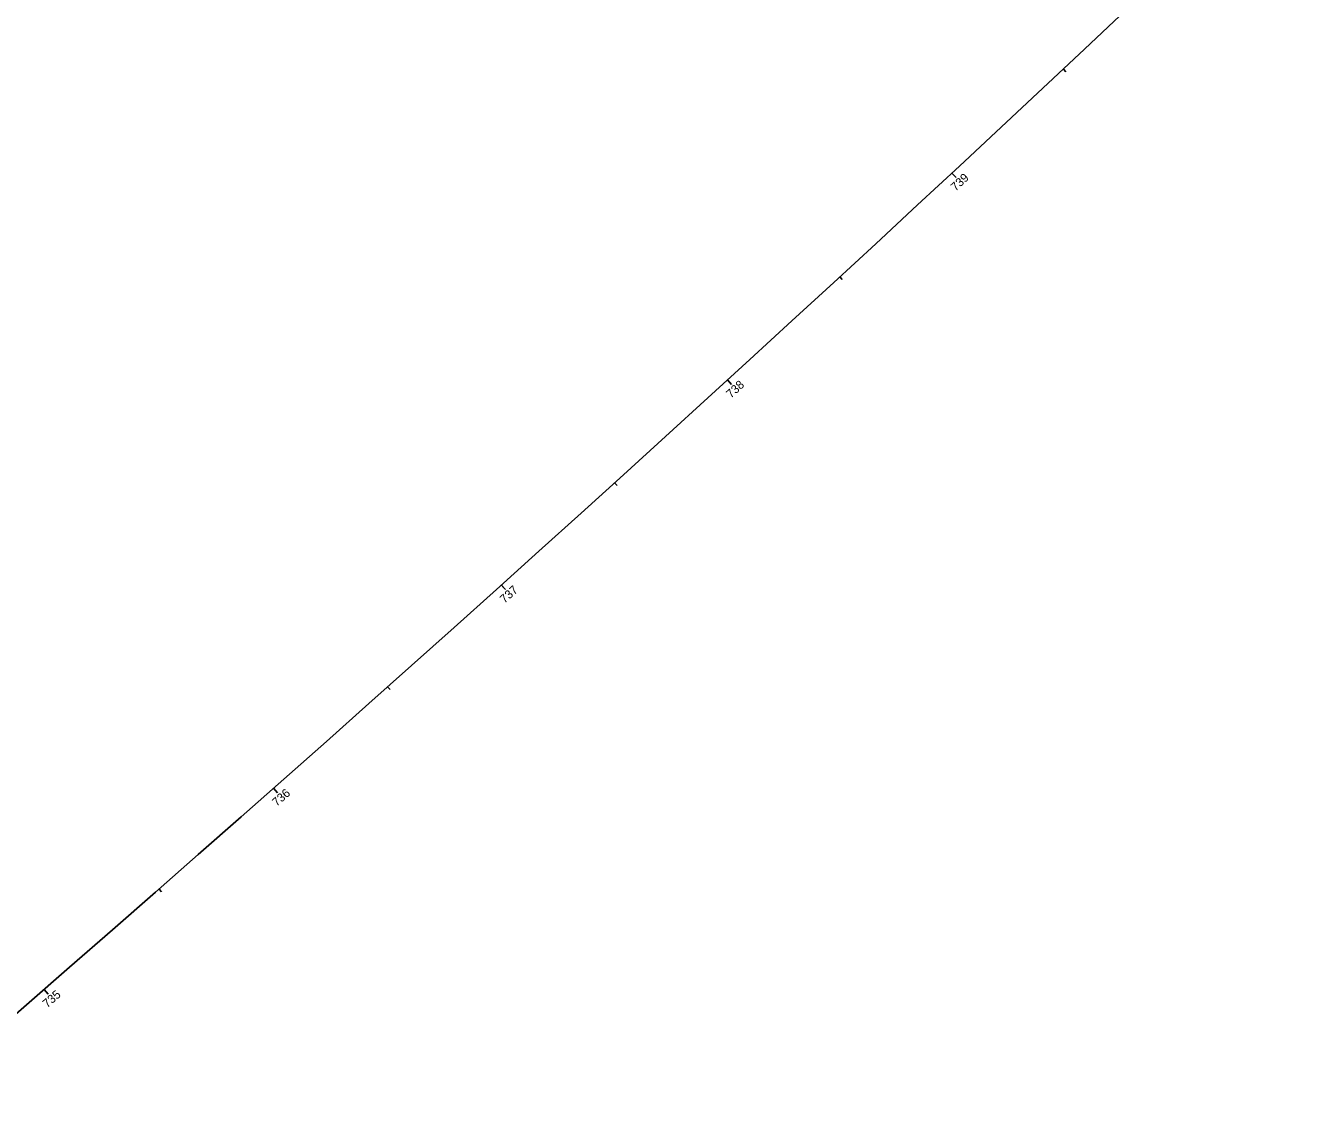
# Model space of a CAD drawing. Extents: x 1492452 to 1496782, y 514026 to 517659.
# Drawn here: x 1494477.9 to 1494892.9, y 515479.1 to 515833 of the extents above; entities that cross this region are included whole.
import ezdxf

# ---------------------------------------------------------------- set-up
doc = ezdxf.new("R2010")
doc.units = 0
for name, color, linetype in [('Default', 7, 'Continuous'), ('DT_X_TIN_Hull', 7, 'Continuous'), ('GE_X_Cells', 7, 'Continuous'), ('UT_X_Water_Cells', 7, 'Continuous'), ('VG_X_Cells', 7, 'Continuous')]:
    doc.layers.add(name, color=color, linetype=linetype)

msp = doc.modelspace()

# ---------------------------------------------------------------- linework, layer by layer
at = {"layer": 'Default'}
msp.add_arc((1486425.91, 524780.42), 12277.67, 302.444021, 313.600151, dxfattribs=at)
at = {"layer": 'DT_X_TIN_Hull'}
for p, q in [((1494818.06, 515818.67), (1494818.88, 515817.79)), ((1494781.5, 515784.57), (1494782.86, 515783.1)), ((1494744.79, 515750.61), (1494745.6, 515749.73)), ((1494707.95, 515716.81), (1494709.3, 515715.34)), ((1494670.97, 515683.16), (1494671.78, 515682.27)), ((1494633.85, 515649.66), (1494635.19, 515648.17)), ((1494596.6, 515616.31), (1494597.4, 515615.41)), ((1494559.21, 515583.11), (1494560.54, 515581.61)), ((1494521.69, 515550.06), (1494522.48, 515549.16)), ((1494484.03, 515517.17), (1494485.35, 515515.66))]:
    msp.add_line(p, q, dxfattribs=at)
at = {"layer": 'GE_X_Cells'}
msp.add_arc((1486425.91, 524780.42), 12277.67, 302.444021, 313.600151, dxfattribs=at)
at = {"layer": 'UT_X_Water_Cells'}
for p, q in [((1494781.5, 515784.57), (1494782.31, 515783.69)), ((1494707.95, 515716.81), (1494708.76, 515715.93)), ((1494633.85, 515649.66), (1494634.66, 515648.76)), ((1494559.21, 515583.11), (1494560.01, 515582.21)), ((1494484.03, 515517.17), (1494485.35, 515515.66))]:
    msp.add_line(p, q, dxfattribs=at)
at = {"layer": 'VG_X_Cells'}
msp.add_line((1494484.03, 515517.17), (1494484.82, 515516.26), dxfattribs=at)

# ---------------------------------------------------------------- texts
at = {"layer": 'DT_X_TIN_Hull'}
for s, rotation, p in [('739', 42.8868, (1494782.72, 515778.47)), ('738', 42.4201, (1494709.1, 515710.69)), ('737', 41.9534, (1494634.91, 515643.48)), ('736', 41.4868, (1494560.26, 515576.96)), ('735', 41.0201, (1494485.03, 515511.01))]:
    msp.add_text(s, height=2.8, rotation=rotation, dxfattribs=at).set_placement(p)
at = {"layer": 'UT_X_Water_Cells'}
msp.add_text('735', height=2.8, rotation=41.0201, dxfattribs=at).set_placement((1494485.03, 515511.01))

doc.saveas('drawing.dxf')
